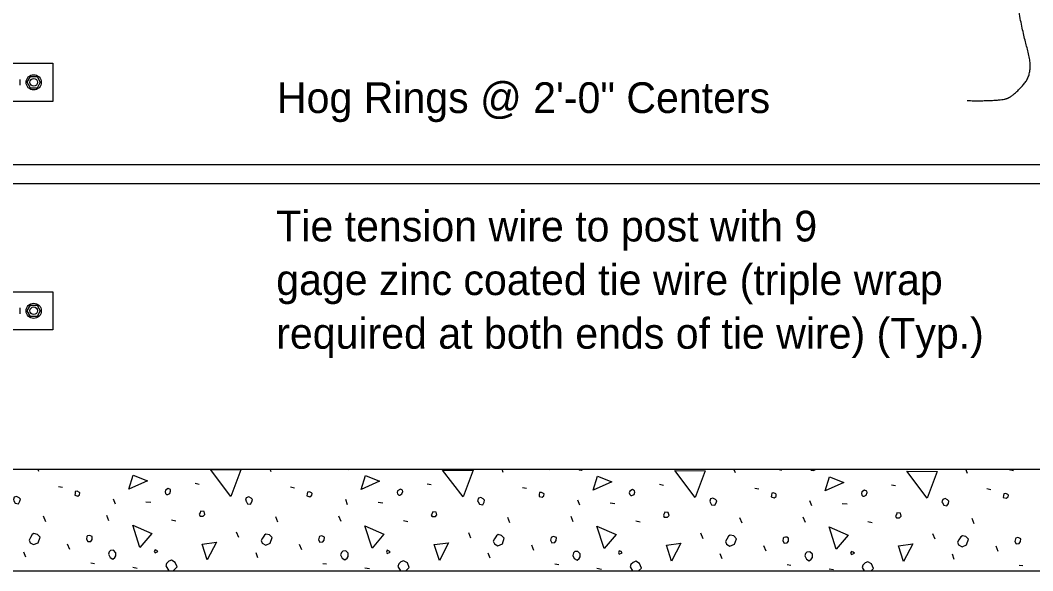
# Model space of a CAD drawing. Extents: x 0.5 to 39.7, y 0.9 to 25.6.
# Drawn here: x 12.4 to 19.05, y 13.47 to 17.08 of the extents above; entities that cross this region are included whole.
import ezdxf

# ---------------------------------------------------------------- set-up
doc = ezdxf.new("R2010")
doc.units = 0
for name, color, linetype in [('Dimension', 7, 'Continuous'), ('Miscellaneous', 7, 'Continuous'), ('SteelMisc', 7, 'Continuous'), ('SupstrConc', 7, 'Continuous'), ('TextStructures', 7, 'Continuous')]:
    doc.layers.add(name, color=color, linetype=linetype)

msp = doc.modelspace()

# ---------------------------------------------------------------- linework, layer by layer
at = {"layer": 'Dimension'}
msp.add_open_spline([(18.6159, 16.5559), (18.8387, 16.5523), (18.9236, 16.5913), (19.0545, 16.74), (18.9696, 17.0374), (18.9272, 17.3027)], degree=2, dxfattribs=at)
at = {"layer": 'Miscellaneous'}
for p, q in [((12.5219, 14.122), (12.5167, 14.1361)), ((14.0457, 14.1184), (14.0392, 14.1361)), ((15.5695, 14.1149), (15.5617, 14.1361)), ((15.8647, 14.1361), (15.8718, 14.1344)), ((17.0933, 14.1114), (17.0842, 14.1361)), ((17.3744, 14.1361), (17.3956, 14.1308)), ((18.6171, 14.1078), (18.6067, 14.1361)), ((18.8911, 14.1344), (18.9194, 14.1273)), ((13.5472, 14.0442), (13.5737, 14.0389)), ((15.071, 14.0407), (15.0975, 14.0354)), ((16.5948, 14.0371), (16.6213, 14.0318)), ((18.1186, 14.0336), (18.1451, 14.0283)), ((12.6492, 14.023), (12.6757, 14.0177)), ((14.173, 14.0194), (14.1995, 14.0141)), ((15.6968, 14.0159), (15.7233, 14.0106)), ((17.2206, 14.0124), (17.2471, 14.0071)), ((18.7444, 14.0088), (18.7709, 14.0035)), ((13.0239, 13.9063), (13.0115, 13.9399)), ((13.2237, 13.9222), (13.2555, 13.9187)), ((14.5477, 13.9028), (14.5354, 13.9364)), ((14.7475, 13.9187), (14.7793, 13.9151)), ((16.0716, 13.8992), (16.0592, 13.9328)), ((16.2713, 13.9151), (16.3031, 13.9116)), ((17.5954, 13.8957), (17.583, 13.9293)), ((17.7951, 13.9116), (17.8269, 13.9081)), ((12.5661, 13.7914), (12.5519, 13.8268)), ((12.9815, 13.7967), (12.9674, 13.8321)), ((14.5053, 13.7932), (14.4912, 13.8285)), ((13.3916, 13.8038), (13.4199, 13.7967)), ((14.0899, 13.7879), (14.0757, 13.8232)), ((14.9154, 13.8002), (14.9437, 13.7932)), ((15.6137, 13.7843), (15.5996, 13.8197)), ((16.0291, 13.7896), (16.015, 13.825)), ((16.4392, 13.7967), (16.4675, 13.7896)), ((17.1375, 13.7808), (17.1234, 13.8162)), ((17.5529, 13.7861), (17.5388, 13.8215)), ((17.9631, 13.7932), (17.9913, 13.7861)), ((18.6613, 13.7773), (18.6472, 13.8126)), ((13.8336, 13.6871), (13.8194, 13.7225)), ((15.3574, 13.6836), (15.3432, 13.7189)), ((16.8812, 13.68), (16.867, 13.7154)), ((18.405, 13.6765), (18.3909, 13.7119)), ((12.7234, 13.6093), (12.7093, 13.6447)), ((14.2472, 13.6058), (14.2331, 13.6411)), ((15.771, 13.6023), (15.7569, 13.6376)), ((17.2948, 13.5987), (17.2807, 13.6341)), ((18.8187, 13.5952), (18.8045, 13.6305)), ((12.4353, 13.5581), (12.4229, 13.5916)), ((13.9591, 13.5545), (13.9467, 13.5881)), ((15.4829, 13.551), (15.4705, 13.5846)), ((17.0067, 13.5475), (16.9943, 13.581)), ((18.5305, 13.5439), (18.5181, 13.5775)), ((12.8613, 13.5209), (12.886, 13.5174)), ((14.3851, 13.5174), (14.4099, 13.5139)), ((15.9089, 13.5139), (15.9337, 13.5103)), ((17.4327, 13.5103), (17.4575, 13.5068)), ((18.9565, 13.5068), (18.9813, 13.5033)), ((13.1371, 13.4927), (13.1671, 13.4873)), ((14.6609, 13.4891), (14.6909, 13.4838)), ((16.1847, 13.4856), (16.2147, 13.4803)), ((17.7085, 13.482), (17.7386, 13.4767))]:
    msp.add_line(p, q, dxfattribs=at)
for points in [[(13.1123, 14.0053), (13.1406, 14.0972), (13.2343, 14.0601), (13.1123, 14.0053)], [(13.7823, 13.9576), (13.6479, 14.1344), (13.8477, 14.1326), (13.7823, 13.9576)], [(14.5442, 14.1361), (14.5566, 14.1344), (14.5607, 14.1361)], [(14.6361, 14.0018), (14.6644, 14.0937), (14.7581, 14.0566), (14.6361, 14.0018)], [(15.3061, 13.954), (15.1718, 14.1308), (15.3715, 14.129), (15.3061, 13.954)], [(16.0645, 14.1361), (16.068, 14.1326)], [(16.068, 14.1326), (16.0804, 14.1308), (16.0928, 14.1361)], [(16.8299, 13.9505), (16.6956, 14.1273), (16.8953, 14.1255), (16.8299, 13.9505)], [(17.5848, 14.1361), (17.5918, 14.129)], [(17.5918, 14.129), (17.6042, 14.1273), (17.6166, 14.1326), (17.6178, 14.1361)], [(18.3537, 13.947), (18.2194, 14.1237), (18.4191, 14.122), (18.3537, 13.947)], [(16.1599, 13.9982), (16.1882, 14.0902), (16.2819, 14.053), (16.1599, 13.9982)], [(17.6838, 13.9947), (17.712, 14.0866), (17.8057, 14.0495), (17.6838, 13.9947)], [(12.757, 13.9646), (12.7764, 13.9593), (12.7888, 13.9682), (12.7906, 13.9806), (12.787, 13.9841), (12.7729, 13.9912), (12.7605, 13.9894), (12.7588, 13.977), (12.757, 13.9646)], [(13.3598, 13.9699), (13.3669, 13.9699), (13.381, 13.977), (13.3863, 13.9929), (13.3845, 14.0018), (13.3704, 14.0088), (13.3527, 13.9982), (13.3492, 13.9876), (13.3527, 13.977), (13.3598, 13.9699)], [(14.2808, 13.9611), (14.3003, 13.9558), (14.3126, 13.9646), (14.3144, 13.977), (14.3109, 13.9806), (14.2967, 13.9876), (14.2843, 13.9859), (14.2826, 13.9735), (14.2808, 13.9611)], [(14.8836, 13.9664), (14.8907, 13.9664), (14.9048, 13.9735), (14.9101, 13.9894), (14.9084, 13.9982), (14.8942, 14.0053), (14.8765, 13.9947), (14.873, 13.9841), (14.8765, 13.9735), (14.8836, 13.9664)], [(15.8046, 13.9576), (15.8241, 13.9523), (15.8364, 13.9611), (15.8382, 13.9735), (15.8347, 13.977), (15.8205, 13.9841), (15.8082, 13.9823), (15.8064, 13.9699), (15.8046, 13.9576)], [(16.4074, 13.9629), (16.4145, 13.9629), (16.4286, 13.9699), (16.4339, 13.9859), (16.4322, 13.9947), (16.418, 14.0018), (16.4004, 13.9912), (16.3968, 13.9806), (16.4004, 13.9699), (16.4074, 13.9629)], [(17.3284, 13.954), (17.3479, 13.9487), (17.3603, 13.9576), (17.362, 13.9699), (17.3585, 13.9735), (17.3443, 13.9806), (17.332, 13.9788), (17.3302, 13.9664), (17.3284, 13.954)], [(17.9312, 13.9593), (17.9383, 13.9593), (17.9525, 13.9664), (17.9578, 13.9823), (17.956, 13.9912), (17.9419, 13.9982), (17.9242, 13.9876), (17.9206, 13.977), (17.9242, 13.9664), (17.9312, 13.9593)], [(18.8523, 13.9505), (18.8717, 13.9452), (18.8841, 13.954), (18.8858, 13.9664), (18.8823, 13.9699), (18.8682, 13.977), (18.8558, 13.9753), (18.854, 13.9629), (18.8523, 13.9505)], [(12.3575, 13.9293), (12.3663, 13.9134), (12.3875, 13.9098), (12.3964, 13.9258), (12.3999, 13.9399), (12.3911, 13.9487), (12.3752, 13.9576), (12.3592, 13.9523), (12.3539, 13.9364), (12.3575, 13.9293)], [(13.8813, 13.9258), (13.8901, 13.9098), (13.9113, 13.9063), (13.9202, 13.9222), (13.9237, 13.9364), (13.9149, 13.9452), (13.899, 13.954), (13.8831, 13.9487), (13.8778, 13.9328), (13.8813, 13.9258)], [(15.4051, 13.9222), (15.4139, 13.9063), (15.4352, 13.9028), (15.444, 13.9187), (15.4475, 13.9328), (15.4387, 13.9417), (15.4228, 13.9505), (15.4069, 13.9452), (15.4016, 13.9293), (15.4051, 13.9222)], [(16.9289, 13.9187), (16.9378, 13.9028), (16.959, 13.8992), (16.9678, 13.9151), (16.9713, 13.9293), (16.9625, 13.9381), (16.9466, 13.947), (16.9307, 13.9417), (16.9254, 13.9258), (16.9289, 13.9187)], [(18.4527, 13.9151), (18.4616, 13.8992), (18.4828, 13.8957), (18.4916, 13.9116), (18.4952, 13.9258), (18.4863, 13.9346), (18.4704, 13.9434), (18.4545, 13.9381), (18.4492, 13.9222), (18.4527, 13.9151)], [(13.579, 13.8285), (13.6002, 13.8285), (13.6108, 13.8391), (13.6055, 13.8586), (13.5825, 13.8603), (13.579, 13.8497), (13.5737, 13.8409), (13.579, 13.8285), (13.5755, 13.8321)], [(15.1028, 13.825), (15.124, 13.825), (15.1346, 13.8356), (15.1293, 13.855), (15.1064, 13.8568), (15.1028, 13.8462), (15.0975, 13.8374), (15.1028, 13.825), (15.0993, 13.8285)], [(16.6266, 13.8215), (16.6478, 13.8215), (16.6585, 13.8321), (16.6531, 13.8515), (16.6302, 13.8533), (16.6266, 13.8427), (16.6213, 13.8338), (16.6266, 13.8215), (16.6231, 13.825)], [(18.1504, 13.8179), (18.1717, 13.8179), (18.1823, 13.8285), (18.177, 13.848), (18.154, 13.8497), (18.1504, 13.8391), (18.1451, 13.8303), (18.1504, 13.8179), (18.1469, 13.8215)], [(13.1848, 13.6217), (13.1371, 13.7684), (13.2626, 13.7136), (13.1848, 13.6217)], [(14.7086, 13.6182), (14.6609, 13.7649), (14.7864, 13.7101), (14.7086, 13.6182)], [(16.2324, 13.6146), (16.1847, 13.7614), (16.3102, 13.7066), (16.2324, 13.6146)], [(12.4635, 13.6535), (12.4865, 13.6411), (12.5166, 13.6535), (12.5289, 13.6906), (12.5113, 13.7083), (12.4883, 13.7136), (12.4777, 13.7066), (12.4653, 13.6871), (12.4565, 13.6712), (12.4635, 13.6535)], [(12.833, 13.6765), (12.8418, 13.6606), (12.8613, 13.6624), (12.8701, 13.6747), (12.8719, 13.6942), (12.8595, 13.6995), (12.8507, 13.7012), (12.8401, 13.6977), (12.8365, 13.6942), (12.833, 13.6765)], [(13.9874, 13.65), (14.0103, 13.6376), (14.0404, 13.65), (14.0528, 13.6871), (14.0351, 13.7048), (14.0121, 13.7101), (14.0015, 13.703), (13.9891, 13.6836), (13.9803, 13.6677), (13.9874, 13.65)], [(14.3568, 13.673), (14.3657, 13.6571), (14.3851, 13.6588), (14.3939, 13.6712), (14.3957, 13.6906), (14.3833, 13.6959), (14.3745, 13.6977), (14.3639, 13.6942), (14.3604, 13.6906), (14.3568, 13.673)], [(15.5112, 13.6464), (15.5342, 13.6341), (15.5642, 13.6464), (15.5766, 13.6836), (15.5589, 13.7012), (15.5359, 13.7066), (15.5253, 13.6995), (15.5129, 13.68), (15.5041, 13.6641), (15.5112, 13.6464)], [(15.8806, 13.6694), (15.8895, 13.6535), (15.9089, 13.6553), (15.9178, 13.6677), (15.9195, 13.6871), (15.9072, 13.6924), (15.8983, 13.6942), (15.8877, 13.6906), (15.8842, 13.6871), (15.8806, 13.6694)], [(17.035, 13.6429), (17.058, 13.6305), (17.088, 13.6429), (17.1004, 13.68), (17.0827, 13.6977), (17.0597, 13.703), (17.0491, 13.6959), (17.0368, 13.6765), (17.0279, 13.6606), (17.035, 13.6429)], [(17.7562, 13.6111), (17.7085, 13.7578), (17.834, 13.703), (17.7562, 13.6111)], [(18.5588, 13.6394), (18.5818, 13.627), (18.6118, 13.6394), (18.6242, 13.6765), (18.6065, 13.6942), (18.5836, 13.6995), (18.5729, 13.6924), (18.5606, 13.673), (18.5517, 13.6571), (18.5588, 13.6394)], [(13.6267, 13.5404), (13.5931, 13.6447), (13.6868, 13.6571), (13.6267, 13.5404)], [(15.1505, 13.5368), (15.117, 13.6411), (15.2107, 13.6535), (15.1505, 13.5368)], [(16.6744, 13.5333), (16.6408, 13.6376), (16.7345, 13.65), (16.6744, 13.5333)], [(17.4044, 13.6659), (17.4133, 13.65), (17.4327, 13.6518), (17.4416, 13.6641), (17.4433, 13.6836), (17.431, 13.6889), (17.4221, 13.6906), (17.4115, 13.6871), (17.408, 13.6836), (17.4044, 13.6659)], [(18.1982, 13.5298), (18.1646, 13.6341), (18.2583, 13.6464), (18.1982, 13.5298)], [(18.9283, 13.6624), (18.9371, 13.6464), (18.9565, 13.6482), (18.9654, 13.6606), (18.9672, 13.68), (18.9548, 13.6853), (18.9459, 13.6871), (18.9353, 13.6836), (18.9318, 13.68), (18.9283, 13.6624)], [(12.978, 13.5775), (12.9886, 13.5563), (13.0062, 13.5457), (13.0204, 13.5563), (13.0275, 13.5669), (13.0275, 13.5881), (13.0115, 13.604), (12.9921, 13.6023), (12.9833, 13.5934), (12.978, 13.5775)], [(13.2838, 13.5863), (13.3032, 13.5952), (13.2962, 13.6023), (13.2838, 13.6076), (13.2785, 13.5952), (13.2838, 13.5863)], [(14.5018, 13.574), (14.5124, 13.5528), (14.5301, 13.5421), (14.5442, 13.5528), (14.5513, 13.5634), (14.5513, 13.5846), (14.5354, 13.6005), (14.5159, 13.5987), (14.5071, 13.5899), (14.5018, 13.574)], [(14.8076, 13.5828), (14.827, 13.5916), (14.82, 13.5987), (14.8076, 13.604), (14.8023, 13.5916), (14.8076, 13.5828)], [(16.0256, 13.5704), (16.0362, 13.5492), (16.0539, 13.5386), (16.068, 13.5492), (16.0751, 13.5598), (16.0751, 13.581), (16.0592, 13.5969), (16.0397, 13.5952), (16.0309, 13.5863), (16.0256, 13.5704)], [(16.3314, 13.5793), (16.3509, 13.5881), (16.3438, 13.5952), (16.3314, 13.6005), (16.3261, 13.5881), (16.3314, 13.5793)], [(17.5494, 13.5669), (17.56, 13.5457), (17.5777, 13.5351), (17.5918, 13.5457), (17.5989, 13.5563), (17.5989, 13.5775), (17.583, 13.5934), (17.5635, 13.5916), (17.5547, 13.5828), (17.5494, 13.5669)], [(17.8552, 13.5757), (17.8747, 13.5846), (17.8676, 13.5916), (17.8552, 13.5969), (17.8499, 13.5846), (17.8552, 13.5757)], [(13.4038, 13.4695), (13.4093, 13.475), (13.4287, 13.4944), (13.4164, 13.5245), (13.3916, 13.5386), (13.3739, 13.5315), (13.3598, 13.5174), (13.3545, 13.5015)], [(13.3545, 13.5015), (13.3743, 13.4695)], [(14.9311, 13.4695), (14.9331, 13.4714), (14.9526, 13.4909), (14.9402, 13.5209), (14.9154, 13.5351), (14.8978, 13.528), (14.8836, 13.5139), (14.8783, 13.498)], [(14.8783, 13.498), (14.896, 13.4695)], [(16.4585, 13.4695), (16.4764, 13.4873), (16.464, 13.5174), (16.4392, 13.5315), (16.4216, 13.5245), (16.4074, 13.5103), (16.4021, 13.4944)], [(16.4021, 13.4944), (16.4176, 13.4695)], [(17.9858, 13.4695), (18.0002, 13.4838), (17.9878, 13.5139), (17.9631, 13.528), (17.9454, 13.5209), (17.9312, 13.5068), (17.9259, 13.4909)], [(17.9259, 13.4909), (17.9392, 13.4695)]]:
    msp.add_lwpolyline(points, dxfattribs=at)
at = {"layer": 'SteelMisc'}
for p, q in [((11.8002, 16.801), (12.6122, 16.801)), ((12.6122, 16.801), (12.6122, 16.551)), ((12.399, 16.6566), (12.399, 16.6955)), ((12.6122, 16.551), (11.8002, 16.551)), ((11.8002, 15.301), (12.6122, 15.301)), ((12.6122, 15.301), (12.6122, 15.051)), ((12.399, 15.1566), (12.399, 15.1955)), ((12.6122, 15.051), (11.8002, 15.051))]:
    msp.add_line(p, q, dxfattribs=at)
for points in [[(12.4655, 16.7135), (12.5089, 16.7135), (12.5305, 16.676), (12.5089, 16.6385), (12.4655, 16.6385), (12.4439, 16.676)], [(12.4655, 15.2135), (12.5089, 15.2135), (12.5305, 15.176), (12.5089, 15.1385), (12.4655, 15.1385), (12.4439, 15.176)]]:
    msp.add_lwpolyline(points, close=True, dxfattribs=at)
for centre, radius in [((12.4872, 16.676), 0.05), ((12.4872, 16.676), 0.025), ((12.4872, 15.176), 0.05), ((12.4872, 15.176), 0.025)]:
    msp.add_circle(centre, radius, dxfattribs=at)
at = {"layer": 'SupstrConc'}
for p, q in [((12.3521, 16.1361), (22.0604, 16.1361)), ((12.3521, 16.0111), (22.0604, 16.0111)), ((0.8193, 14.1361), (23.5931, 14.1361)), ((0.8193, 13.4695), (23.5931, 13.4695))]:
    msp.add_line(p, q, dxfattribs=at)

# ---------------------------------------------------------------- texts
at = {"layer": 'Dimension'}
for s, p in [('Tie tension wire to post with 9 ', (14.0794, 15.6312)), ('gage zinc coated tie wire (triple wrap ', (14.0794, 15.2792)), ('required at both ends of tie wire) (Typ.)', (14.0794, 14.9272))]:
    msp.add_text(s, height=0.2016, dxfattribs=at).set_placement(p)
at = {"layer": 'TextStructures'}
msp.add_text('Hog Rings @ 2\'-0" Centers', height=0.2016, dxfattribs=at).set_placement((14.0841, 16.4746))

doc.saveas('drawing.dxf')
